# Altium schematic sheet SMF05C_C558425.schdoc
size 127 x 101 mm
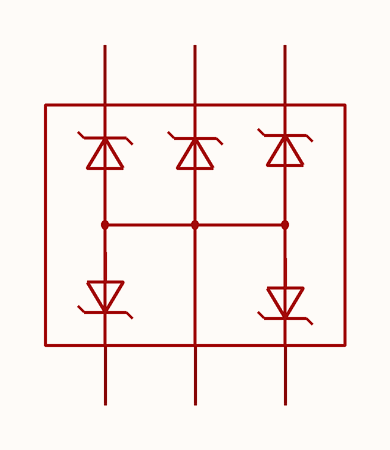
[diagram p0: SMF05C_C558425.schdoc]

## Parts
D?  smf05c  [SC-70-6_L2.0-W1.3-P0.65-LS2.1-BR]  (value not drawn)

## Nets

Not connected (* = marked no-connect by the designer): D? 1 2 3 4 5 6

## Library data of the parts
D? = smf05c: 极性:单向;反向截止电压(Vrwm):5V;钳位电压:12V;峰值脉冲电流(Ipp):10A@8/20us;峰值脉冲功率(Ppp):200W@8/20us;击穿电压:6V;; Manufacturer: TECH PUBLIC(台舟); Symbol: SMF05C_C558425; AddInBom: yes; ModelId: 7779600a2eb94c6fae04993c10cd58cb; ModelName: SC-70-6_L2.0-W1.3-H1.0-P0.65; ModelTransform: 82.677,78.74,0,0,0,0,0,0,0; Polarity: 单向; Reverse Stand-Off Voltage (Vrwm): 5V; Clamping Voltage: 12V; Voltage - Breakdown: 6V; Reverse Leakage Current (Ir): 100nA; Number of Channels: 五路; level of protection: IEC 61000-4-2；IEC 61000-4-4；IEC 61000-4-5; Type: ESD; Junction Capacitance: 80pF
